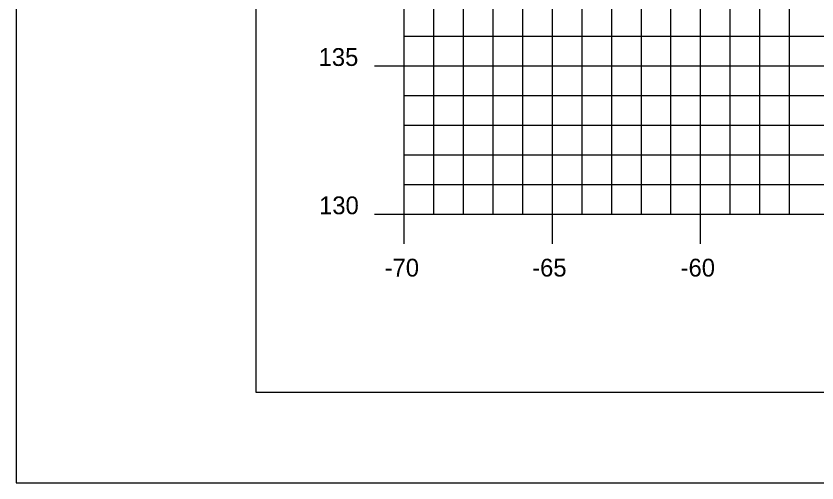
# Model space of a CAD drawing. Extents: x 1146746 to 1146916, y 608981 to 609091.
# Drawn here: x 1146746.33 to 1146773.35, y 608981.28 to 608997.02 of the extents above; entities that cross this region are included whole.
import ezdxf

# ---------------------------------------------------------------- set-up
doc = ezdxf.new("R2010")
doc.units = 0
for name, color, linetype in [('BORDER', 7, 'Continuous'), ('H_V ANNOTATION', 7, 'Continuous'), ('MAJOR', 7, 'Continuous'), ('MINOR', 7, 'Continuous'), ('PLOT BOUNDARY', 7, 'Continuous')]:
    doc.layers.add(name, color=color, linetype=linetype)

msp = doc.modelspace()

# ---------------------------------------------------------------- linework, layer by layer
at = {"layer": 'BORDER'}
msp.add_lwpolyline([(1146754.428, 608984.335), (1146914.428, 608984.335), (1146914.428, 609089.335), (1146754.428, 609089.335)], close=True, dxfattribs=at)
at = {"layer": 'MAJOR'}
for p, q in [((1146759.428, 608990.335), (1146759.428, 609010.335)), ((1146759.428, 608990.335), (1146759.428, 609010.335)), ((1146764.428, 608990.335), (1146764.428, 609010.335)), ((1146769.428, 608990.335), (1146769.428, 609010.335)), ((1146758.426, 608995.335), (1146759.428, 608995.335)), ((1146759.428, 608995.335), (1146899.428, 608995.335)), ((1146758.426, 608990.335), (1146759.428, 608990.335)), ((1146759.428, 608990.335), (1146899.428, 608990.335)), ((1146759.428, 608990.335), (1146899.428, 608990.335)), ((1146759.428, 608989.333), (1146759.428, 608990.335)), ((1146764.428, 608989.333), (1146764.428, 608990.335)), ((1146769.428, 608989.333), (1146769.428, 608990.335))]:
    msp.add_line(p, q, dxfattribs=at)
at = {"layer": 'MINOR'}
for p, q in [((1146759.428, 608990.335), (1146759.428, 609010.335)), ((1146760.428, 608990.335), (1146760.428, 609010.335)), ((1146761.428, 608990.335), (1146761.428, 609010.335)), ((1146762.428, 608990.335), (1146762.428, 609010.335)), ((1146763.428, 608990.335), (1146763.428, 609010.335)), ((1146765.428, 608990.335), (1146765.428, 609010.335)), ((1146766.428, 608990.335), (1146766.428, 609010.335)), ((1146767.428, 608990.335), (1146767.428, 609010.335)), ((1146768.428, 608990.335), (1146768.428, 609010.335)), ((1146770.428, 608990.335), (1146770.428, 609010.335)), ((1146771.428, 608990.335), (1146771.428, 609010.335)), ((1146772.428, 608990.335), (1146772.428, 609010.335)), ((1146759.428, 608996.335), (1146899.428, 608996.335)), ((1146759.428, 608996.335), (1146760.43, 608996.335)), ((1146759.428, 608994.335), (1146899.428, 608994.335)), ((1146759.428, 608994.335), (1146760.43, 608994.335)), ((1146759.428, 608993.335), (1146899.428, 608993.335)), ((1146759.428, 608993.335), (1146760.43, 608993.335)), ((1146759.428, 608992.335), (1146899.428, 608992.335)), ((1146759.428, 608992.335), (1146760.43, 608992.335)), ((1146759.428, 608991.335), (1146899.428, 608991.335)), ((1146759.428, 608991.335), (1146760.43, 608991.335))]:
    msp.add_line(p, q, dxfattribs=at)
at = {"layer": 'PLOT BOUNDARY'}
msp.add_lwpolyline([(1146746.335, 608981.276), (1146916.335, 608981.276), (1146916.335, 609091.276), (1146746.335, 609091.276)], close=True, dxfattribs=at)

# ---------------------------------------------------------------- texts
at = {"layer": 'H_V ANNOTATION'}
for s, p in [('135', (1146756.542, 608995.335)), ('130', (1146756.558, 608990.335)), ('-70', (1146758.769, 608988.235)), ('-65', (1146763.745, 608988.235)), ('-60', (1146768.753, 608988.235))]:
    msp.add_text(s, height=0.6, dxfattribs=at).set_placement(p)
at = {"layer": 'MAJOR'}
msp.add_text('-', height=0.006, dxfattribs=at).set_placement((1146759.423, 608990.335))

doc.saveas('drawing.dxf')
